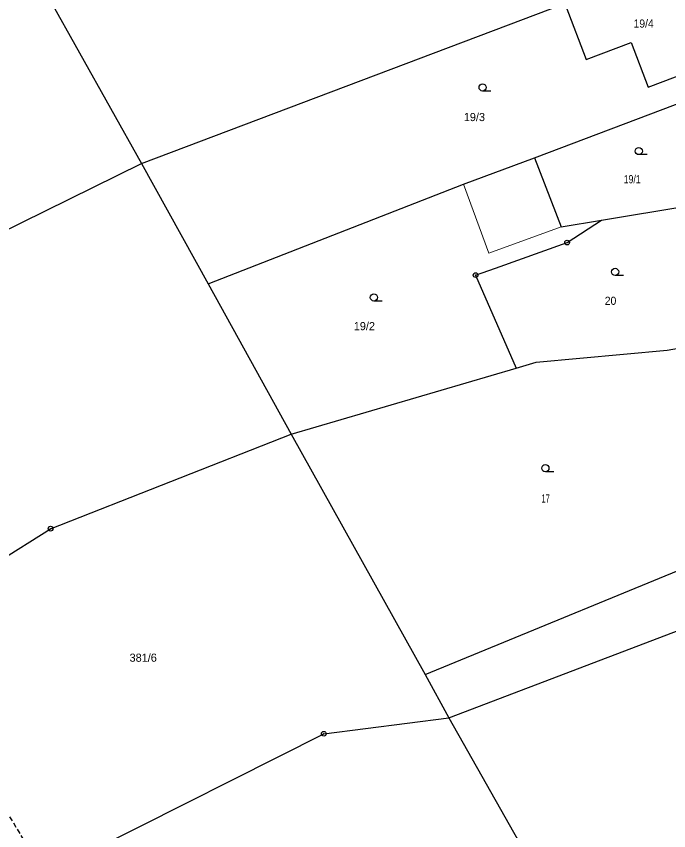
# Model space of a CAD drawing. Extents: x -592965 to -592390, y -1145071 to -1144631.
# Drawn here: x -592769.5 to -592701.3, y -1144793.9 to -1144708.7 of the extents above; entities that cross this region are included whole.
import ezdxf

# ---------------------------------------------------------------- set-up
doc = ezdxf.new("R2010")
doc.units = 0
doc.header["$LTSCALE"] = 0.17
doc.linetypes.add('MEDIUM_DASHED', pattern=[4.5, 3, -1.5])
doc.layers.add('4', color=7, linetype='Continuous', lineweight=25)

msp = doc.modelspace()

# ---------------------------------------------------------------- linework, layer by layer
at = {"layer": '4'}
for p, q in [((-592756.36, -1144724.09), (-592691.2, -1144699.44)), ((-592769.91, -1144699.89), (-592756.36, -1144724.09)), ((-592712.03, -1144707.64), (-592709.92, -1144713.22)), ((-592709.92, -1144713.22), (-592705.2, -1144711.46)), ((-592705.2, -1144711.46), (-592703.44, -1144716.13)), ((-592715.29, -1144723.52), (-592685.87, -1144712.37)), ((-592703.44, -1144716.13), (-592697.83, -1144714.01)), ((-592719.855, -1144716.53), (-592720.73, -1144716.53)), ((-592703.535, -1144723.18), (-592704.41, -1144723.18)), ((-592778.78, -1144735.16), (-592756.36, -1144724.09)), ((-592756.36, -1144724.09), (-592749.4, -1144736.7)), ((-592722.74, -1144726.28), (-592715.29, -1144723.52)), ((-592715.29, -1144723.52), (-592712.53, -1144730.71)), ((-592749.4, -1144736.7), (-592722.74, -1144726.28)), ((-592708.3, -1144730.02), (-592697.76, -1144728.29)), ((-592712.53, -1144730.71), (-592708.3, -1144730.02)), ((-592711.9, -1144732.37), (-592708.3, -1144730.02)), ((-592719.39, -1144735.04), (-592711.9, -1144732.37)), ((-592721.46, -1144735.77), (-592719.39, -1144735.04)), ((-592721.46, -1144735.77), (-592717.23, -1144745.51)), ((-592706.005, -1144735.81), (-592706.88, -1144735.81)), ((-592749.4, -1144736.7), (-592740.74, -1144752.39)), ((-592731.215, -1144738.48), (-592732.09, -1144738.48)), ((-592701.44, -1144743.62), (-592691.09, -1144741.71)), ((-592715.12, -1144744.89), (-592701.44, -1144743.62)), ((-592740.74, -1144752.39), (-592717.23, -1144745.51)), ((-592717.23, -1144745.51), (-592715.12, -1144744.89)), ((-592765.88, -1144762.28), (-592740.74, -1144752.39)), ((-592740.74, -1144752.39), (-592726.72, -1144777.51)), ((-592713.295, -1144756.33), (-592714.17, -1144756.33)), ((-592791.59, -1144778.43), (-592765.88, -1144762.28)), ((-592724.27, -1144782.05), (-592691.9, -1144769.72)), ((-592726.72, -1144777.51), (-592724.27, -1144782.05)), ((-592737.33, -1144783.72), (-592724.27, -1144782.05)), ((-592724.27, -1144782.05), (-592705.33, -1144815.45)), ((-592768.57, -1144799.46), (-592737.33, -1144783.72))]:
    msp.add_line(p, q, dxfattribs=at)
at = {"layer": '4', "lineweight": 13}
for p, q in [((-592722.74, -1144726.28), (-592720.07, -1144733.49)), ((-592720.07, -1144733.49), (-592712.53, -1144730.71))]:
    msp.add_line(p, q, dxfattribs=at)
at = {"layer": '4', "linetype": 'MEDIUM_DASHED'}
msp.add_lwpolyline([(-592857.7, -1144647.96), (-592827.25, -1144698.04), (-592798.73, -1144745.3), (-592765.1, -1144800.74), (-592721.92, -1144873.86), (-592693.51, -1144920.47), (-592669.72, -1144961.82), (-592709.34, -1144973.09), (-592761.29, -1144989.89), (-592825.83, -1145034.08), (-592878.88, -1145071.17)], dxfattribs=at)
at = {"layer": '4'}
msp.add_lwpolyline([(-592726.72, -1144777.51), (-592694.03, -1144764.07), (-592686.72, -1144761.06)], dxfattribs=at)
for centre, radius in [((-592720.73, -1144716.155), 0.375), ((-592704.41, -1144722.805), 0.375), ((-592711.9, -1144732.37), 0.25), ((-592711.9, -1144732.37), 0.0164), ((-592706.88, -1144735.435), 0.375), ((-592721.46, -1144735.77), 0.25), ((-592721.46, -1144735.77), 0.0164), ((-592732.09, -1144738.105), 0.375), ((-592714.17, -1144755.955), 0.375), ((-592765.88, -1144762.28), 0.25), ((-592765.88, -1144762.28), 0.0164), ((-592737.33, -1144783.72), 0.25), ((-592737.33, -1144783.72), 0.0164)]:
    msp.add_circle(centre, radius, dxfattribs=at)

# ---------------------------------------------------------------- texts
for s, width, p in [('19/4', 0.95, (-592704.95, -1144709.9)), ('19/1', 0.8, (-592705.98, -1144726.17)), ('20', 0.95, (-592707.96, -1144738.88)), ('17', 0.6, (-592714.57, -1144759.55))]:
    msp.add_text(s, height=0.85, dxfattribs=dict(at, width=width)).set_placement(p)
for s, p in [('19/3', (-592722.69, -1144719.67)), ('19/2', (-592734.19, -1144741.53)), ('381/6', (-592757.62, -1144776.19))]:
    msp.add_text(s, height=0.85, dxfattribs=at).set_placement(p)

doc.saveas('drawing.dxf')
